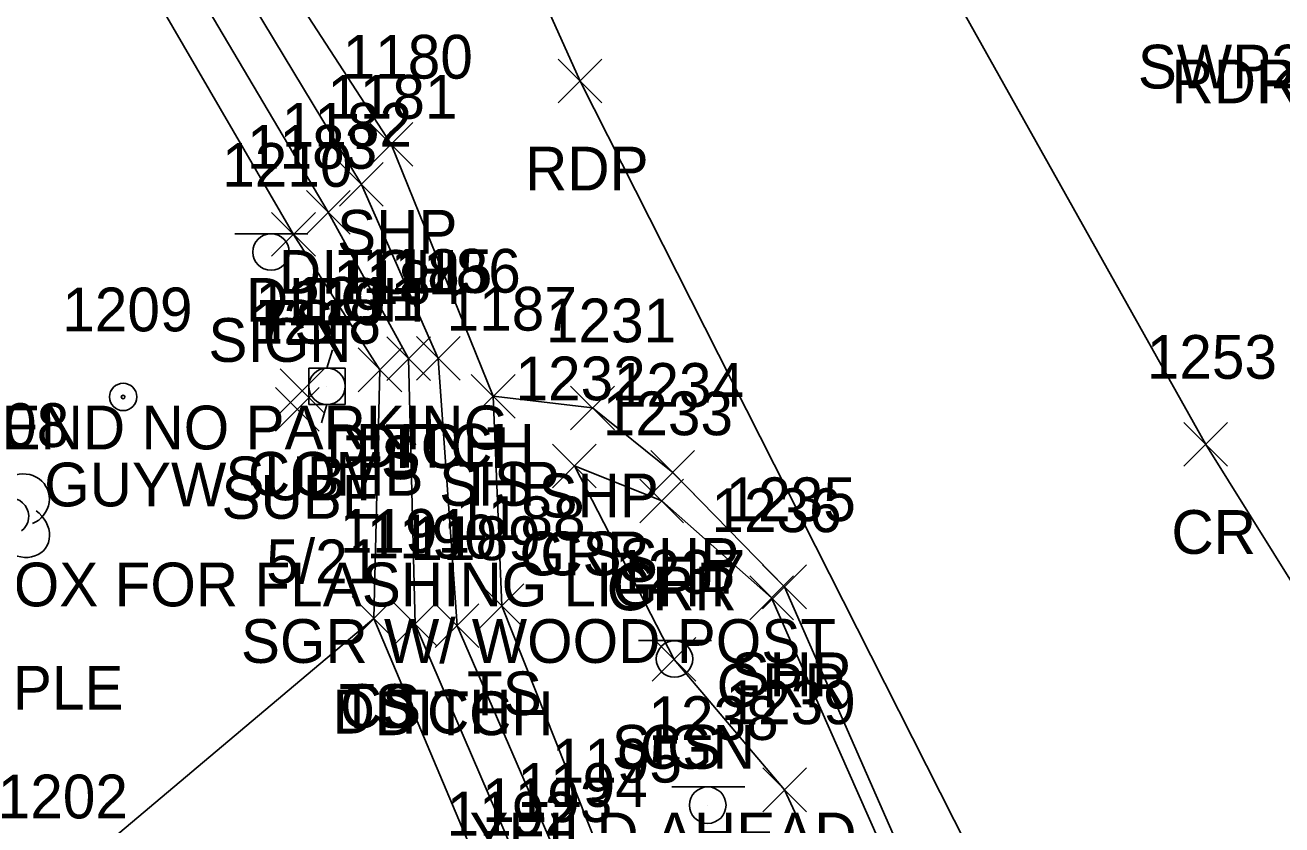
# Model space of a CAD drawing. Extents: x 1504228 to 1506103, y 437717 to 440106.
# Drawn here: x 1505135.1 to 1505192.5, y 438238.1 to 438274.7 of the extents above; entities that cross this region are included whole.
import ezdxf

# ---------------------------------------------------------------- set-up
doc = ezdxf.new("R2010")
doc.units = 0
for name, color, linetype in [('D_A', 7, 'Continuous'), ('D_I', 7, 'Continuous'), ('D_TIC', 7, 'Continuous'), ('DD', 7, 'Continuous'), ('L_A', 7, 'Continuous'), ('L_C', 7, 'Continuous'), ('L_I', 7, 'Continuous'), ('L_TIC', 7, 'Continuous'), ('LELB', 7, 'Continuous'), ('LTD', 7, 'Continuous'), ('P_A', 7, 'Continuous'), ('P_I', 7, 'Continuous'), ('P_TIC', 7, 'Continuous'), ('PET', 7, 'Continuous'), ('PRC', 7, 'Continuous'), ('PSP', 7, 'Continuous'), ('R_A', 7, 'Continuous'), ('R_C', 7, 'Continuous'), ('R_I', 7, 'Continuous'), ('R_TIC', 7, 'Continuous'), ('RGR', 7, 'Continuous'), ('S_A', 7, 'Continuous'), ('S_C', 7, 'Continuous'), ('S_I', 7, 'Continuous'), ('SSGN', 7, 'Continuous'), ('U_A', 7, 'Continuous'), ('U_C', 7, 'Continuous'), ('U_I', 7, 'Continuous'), ('U_TIC', 7, 'Continuous'), ('UP', 7, 'Continuous'), ('UPGW', 7, 'Continuous')]:
    doc.layers.add(name, color=color, linetype=linetype)

msp = doc.modelspace()

# ---------------------------------------------------------------- linework, layer by layer
at = {"layer": 'D_TIC'}
for points in [[(1505149.445, 438266.376), (1505151.445, 438268.376)], [(1505151.445, 438266.376), (1505149.445, 438268.376)], [(1505147.937, 438265.102), (1505149.937, 438267.102)], [(1505149.937, 438265.102), (1505147.937, 438267.102)], [(1505151.605, 438258.415), (1505153.605, 438260.415)], [(1505153.605, 438258.415), (1505151.605, 438260.415)], [(1505152.96, 438258.428), (1505154.96, 438260.428)], [(1505154.96, 438258.428), (1505152.96, 438260.428)], [(1505151.899, 438246.284), (1505153.899, 438248.284)], [(1505153.899, 438246.284), (1505151.899, 438248.284)], [(1505153.819, 438246.207), (1505155.819, 438248.207)], [(1505155.819, 438246.207), (1505153.819, 438248.207)]]:
    msp.add_lwpolyline(points, dxfattribs=at)
at = {"layer": 'DD'}
for points in [[(1505123.23, 438314.656), (1505130.775, 438299.935), (1505150.445, 438267.376), (1505153.96, 438259.428), (1505154.819, 438247.207), (1505159.704, 438235.931), (1505164.132, 438229.451)], [(1505121.248, 438312.943), (1505129.281, 438299.278), (1505148.937, 438266.102), (1505152.605, 438259.415), (1505152.899, 438247.284), (1505158.089, 438235.239), (1505161.473, 438228.418)]]:
    msp.add_lwpolyline(points, dxfattribs=at)
at = {"layer": 'L_TIC'}
for points in [[(1505146.346, 438264.092), (1505148.346, 438266.092)], [(1505148.346, 438264.092), (1505146.346, 438266.092)], [(1505146.346, 438264.092), (1505148.346, 438266.092)], [(1505148.346, 438264.092), (1505146.346, 438266.092)], [(1505150.295, 438257.904), (1505152.295, 438259.904)], [(1505152.295, 438257.904), (1505150.295, 438259.904)], [(1505155.465, 438256.693), (1505157.465, 438258.693)], [(1505157.465, 438256.693), (1505155.465, 438258.693)], [(1505159.179, 438253.51), (1505161.179, 438255.51)], [(1505161.179, 438253.51), (1505159.179, 438255.51)], [(1505155.863, 438247.12), (1505157.863, 438249.12)], [(1505157.863, 438247.12), (1505155.863, 438249.12)], [(1505150.02, 438246.541), (1505152.02, 438248.541)], [(1505152.02, 438246.541), (1505150.02, 438248.541)], [(1505150.02, 438246.541), (1505152.02, 438248.541)], [(1505152.02, 438246.541), (1505150.02, 438248.541)], [(1505163.729, 438244.673), (1505165.729, 438246.673)], [(1505165.729, 438244.673), (1505163.729, 438246.673)], [(1505168.781, 438238.71), (1505170.781, 438240.71)], [(1505170.781, 438238.71), (1505168.781, 438240.71)]]:
    msp.add_lwpolyline(points, dxfattribs=at)
at = {"layer": 'LELB'}
for points in [[(1505072.779, 438294.246), (1505074.28, 438301.778), (1505090.168, 438310.15), (1505097.967, 438315.777), (1505107.308, 438321.068), (1505113.899, 438322.703), (1505119.766, 438311.905), (1505127.938, 438298.439), (1505147.346, 438265.092)], [(1505147.346, 438265.092), (1505151.295, 438258.904), (1505151.02, 438247.541), (1505156.466, 438234.619), (1505159.07, 438229.354), (1505161.306, 438207.965), (1505158.934, 438198.457), (1505143.439, 438200.103), (1505132.424, 438196.394), (1505118.601, 438190.29)], [(1505156.465, 438257.693), (1505156.863, 438248.12), (1505161.265, 438237.042), (1505166.001, 438229.888), (1505173.548, 438226.954), (1505175.53, 438227.278)], [(1505160.179, 438254.51), (1505164.729, 438245.673), (1505169.781, 438239.71), (1505175.53, 438227.278)], [(1505151.02, 438247.541), (1505136.605, 438235.405), (1505116.834, 438228.742), (1505105.312, 438222.915)]]:
    msp.add_lwpolyline(points, dxfattribs=at)
at = {"layer": 'LTD'}
for centre, major_axis, ratio, start_param, end_param in [((1505134.965, 438252.96), (-1.141, -0.483), 0.949671, 1.570796, 4.712389), ((1505134.424, 438252.21), (-0.5, 0.667), 0.989748, 3.141593, 6.283185), ((1505134.924, 438251.543), (-1.09, 0.792), 0.841452, 1.570796, 4.712389)]:
    msp.add_ellipse(centre, major_axis=major_axis, ratio=ratio, start_param=start_param, end_param=end_param, dxfattribs=at)
at = {"layer": 'P_TIC'}
for points in [[(1505159.435, 438271.099), (1505161.435, 438273.099)], [(1505161.435, 438271.099), (1505159.435, 438273.099)], [(1505150.801, 438268.21), (1505152.801, 438270.21)], [(1505152.801, 438268.21), (1505150.801, 438270.21)], [(1505155.465, 438256.693), (1505157.465, 438258.693)], [(1505157.465, 438256.693), (1505155.465, 438258.693)], [(1505160.003, 438256.161), (1505162.003, 438258.161)], [(1505162.003, 438256.161), (1505160.003, 438258.161)], [(1505188.016, 438254.493), (1505190.016, 438256.493)], [(1505190.016, 438254.493), (1505188.016, 438256.493)], [(1505163.671, 438253.213), (1505165.671, 438255.213)], [(1505165.671, 438253.213), (1505163.671, 438255.213)], [(1505168.777, 438247.987), (1505170.777, 438249.987)], [(1505170.777, 438247.987), (1505168.777, 438249.987)]]:
    msp.add_lwpolyline(points, dxfattribs=at)
at = {"layer": 'PET'}
msp.add_lwpolyline([(1505068.915, 438479.856), (1505088.799, 438434.786), (1505098.18, 438413.38), (1505109.535, 438384.969), (1505120.749, 438360.591), (1505130.106, 438339.585), (1505143.01, 438310.872), (1505160.435, 438272.099), (1505181.323, 438230.832), (1505199.453, 438238.762), (1505211.655, 438244.29), (1505203.781, 438257.456), (1505193.868, 438276.083), (1505183.087, 438301.098), (1505168.267, 438328.998), (1505148.647, 438369.04), (1505141.294, 438386.172), (1505109.448, 438444.779), (1505106.082, 438450.67), (1505101.61, 438460.04), (1505094.486, 438475.336), (1505087.609, 438490.541)], dxfattribs=at)
at = {"layer": 'PRC'}
msp.add_lwpolyline([(1505079.068, 438483.546), (1505099.188, 438438.177), (1505118.696, 438394.368), (1505142.43, 438344.291), (1505155.616, 438317.19), (1505174.858, 438280.77), (1505189.016, 438255.493), (1505199.453, 438238.762)], dxfattribs=at)
at = {"layer": 'PSP'}
msp.add_lwpolyline([(1505089.41, 438366.798), (1505096.876, 438357.305), (1505097.995, 438355.39), (1505102.72, 438347.262), (1505117.993, 438324.088), (1505123.23, 438314.656), (1505131.485, 438300.488), (1505151.801, 438269.21), (1505156.465, 438257.693), (1505161.003, 438257.161), (1505164.671, 438254.213), (1505169.777, 438248.987), (1505178.313, 438229.528), (1505181.323, 438230.832)], dxfattribs=at)
at = {"layer": 'R_TIC'}
for points in [[(1505159.179, 438253.51), (1505161.179, 438255.51)], [(1505161.179, 438253.51), (1505159.179, 438255.51)], [(1505163.165, 438251.914), (1505165.165, 438253.914)], [(1505165.165, 438251.914), (1505163.165, 438253.914)], [(1505168.186, 438247.485), (1505170.186, 438249.485)], [(1505170.186, 438247.485), (1505168.186, 438249.485)]]:
    msp.add_lwpolyline(points, dxfattribs=at)
at = {"layer": 'RGR'}
msp.add_lwpolyline([(1505160.179, 438254.51), (1505164.165, 438252.914), (1505169.186, 438248.485), (1505177.609, 438229.457)], dxfattribs=at)
at = {"layer": 'SSGN'}
for p, q in [((1505144.673, 438265.12), (1505148.006, 438265.12)), ((1505146.32, 438264.287), (1505146.32, 438264.287)), ((1505163.102, 438246.527), (1505166.435, 438246.527)), ((1505164.749, 438245.693), (1505164.749, 438245.693)), ((1505164.623, 438239.842), (1505167.956, 438239.842)), ((1505166.27, 438239.009), (1505166.27, 438239.009))]:
    msp.add_line(p, q, dxfattribs=at)
for centre in [(1505146.32, 438264.287), (1505164.749, 438245.693), (1505166.27, 438239.009)]:
    msp.add_circle(centre, 0.833, dxfattribs=at)
at = {"layer": 'U_TIC'}
for points in [[(1505146.743, 438256.943), (1505148.743, 438258.943)], [(1505148.743, 438256.943), (1505146.743, 438258.943)], [(1505146.521, 438256.094), (1505148.521, 438258.094)], [(1505148.521, 438256.094), (1505146.521, 438258.094)]]:
    msp.add_lwpolyline(points, dxfattribs=at)
at = {"layer": 'UP'}
for p, q in [((1505149.125, 438259.817), (1505148.875, 438258.983)), ((1505148.042, 438257.317), (1505148.042, 438258.983)), ((1505148.042, 438258.983), (1505149.708, 438258.983)), ((1505149.708, 438258.983), (1505149.708, 438257.317)), ((1505148.875, 438258.15), (1505148.875, 438258.15)), ((1505149.708, 438257.317), (1505148.042, 438257.317)), ((1505148.625, 438256.483), (1505148.875, 438257.317))]:
    msp.add_line(p, q, dxfattribs=at)
msp.add_circle((1505148.875, 438258.15), 0.833, dxfattribs=at)
at = {"layer": 'UPGW'}
for radius in [0.625, 0.0833]:
    msp.add_circle((1505139.562, 438257.662), radius, dxfattribs=at)

# ---------------------------------------------------------------- texts
at = {"layer": 'D_A'}
for p in [(1505146.681, 438262.376), (1505145.173, 438261.102), (1505148.841, 438254.415), (1505150.196, 438254.428), (1505149.135, 438242.284), (1505151.055, 438242.207)]:
    msp.add_text('DITCH', height=2, dxfattribs=at).set_placement(p)
at = {"layer": 'D_I'}
for s, p in [('1181', (1505148.886, 438270.376)), ('1182', (1505146.811, 438269.102)), ('1185', (1505150.479, 438262.415)), ('1186', (1505151.779, 438262.428)), ('1190', (1505150.686, 438250.284)), ('1189', (1505152.685, 438250.207)), ('1194', (1505157.578, 438238.931)), ('1193', (1505155.963, 438238.239))]:
    msp.add_text(s, height=2, dxfattribs=at).set_placement(p)
at = {"layer": 'L_A'}
for s, p in [('TS', (1505145.755, 438260.092)), ('TS', (1505145.755, 438260.092)), ('TS', (1505149.704, 438253.904)), ('TS', (1505154.874, 438252.693)), ('CS', (1505158.62, 438249.51)), ('TS', (1505155.273, 438243.12)), ('TS', (1505149.429, 438242.541)), ('CS', (1505149.461, 438242.541)), ('CS', (1505163.17, 438240.673))]:
    msp.add_text(s, height=2, dxfattribs=at).set_placement(p)
at = {"layer": 'L_C'}
msp.add_text('M.APPLE', height=2, dxfattribs=at).set_placement((1505127.987, 438243.376))
at = {"layer": 'L_I'}
for s, p in [('1183', (1505145.22, 438268.092)), ('1183', (1505145.22, 438268.092)), ('1184', (1505149.169, 438261.904)), ('1187', (1505154.339, 438260.693)), ('1232', (1505157.486, 438257.51)), ('1208', (1505131.152, 438255.376)), ('1188', (1505154.737, 438251.12)), ('1191', (1505149.461, 438250.541)), ('1191', (1505149.461, 438250.541)), ('1237', (1505162.036, 438248.673)), ('1239', (1505167.08, 438242.71)), ('1195', (1505159.139, 438240.042)), ('1202', (1505133.834, 438238.405)), ('1192', (1505154.34, 438237.619))]:
    msp.add_text(s, height=2, dxfattribs=at).set_placement(p)
at = {"layer": 'P_A'}
for s, p in [('RDP', (1505191.356, 438271.083)), ('RDP', (1505157.923, 438267.099)), ('SHP', (1505149.337, 438264.21)), ('SHP', (1505154, 438252.693)), ('SHP', (1505158.538, 438252.161)), ('CR', (1505187.449, 438250.493)), ('SHP', (1505162.207, 438249.213)), ('SHP', (1505167.313, 438243.987))]:
    msp.add_text(s, height=2, dxfattribs=at).set_placement(p)
at = {"layer": 'P_I'}
for s, p in [('1180', (1505149.589, 438272.21)), ('1187', (1505154.339, 438260.693)), ('1231', (1505158.877, 438260.161)), ('1253', (1505186.323, 438258.493)), ('1234', (1505161.979, 438257.213)), ('1235', (1505167.084, 438251.987))]:
    msp.add_text(s, height=2, dxfattribs=at).set_placement(p)
at = {"layer": 'R_A'}
for s, p in [('SWP2 BS ST', (1505185.915, 438271.759)), ('RDP SWP', (1505187.451, 438271.083)), ('GRR', (1505157.668, 438249.51)), ('GRR', (1505161.654, 438247.914)), ('GRR', (1505166.674, 438243.485))]:
    msp.add_text(s, height=2, dxfattribs=at).set_placement(p)
at = {"layer": 'R_C'}
msp.add_text('SGR W/ WOOD POST', height=2, dxfattribs=at).set_placement((1505144.943, 438245.51))
at = {"layer": 'R_I'}
for s, p in [('1232', (1505157.486, 438257.51)), ('1233', (1505161.473, 438255.914)), ('1236', (1505166.438, 438251.485))]:
    msp.add_text(s, height=2, dxfattribs=at).set_placement(p)
at = {"layer": 'S_A'}
for p in [(1505143.458, 438259.267), (1505161.887, 438240.673)]:
    msp.add_text('SIGN', height=2, dxfattribs=at).set_placement(p)
at = {"layer": 'S_C'}
for s, p in [('END NO PARKING', (1505134.009, 438255.267)), ('YEILD AHEAD', (1505155.383, 438236.673))]:
    msp.add_text(s, height=2, dxfattribs=at).set_placement(p)
at = {"layer": 'S_I'}
for s, p in [('1210', (1505144.088, 438267.267)), ('1237', (1505162.036, 438248.673)), ('1238', (1505163.557, 438241.989))]:
    msp.add_text(s, height=2, dxfattribs=at).set_placement(p)
at = {"layer": 'U_A'}
for s, p in [('GUYW', (1505135.956, 438252.662)), ('SUBT', (1505144.239, 438252.943)), ('COMB', (1505145.261, 438253.15)), ('SUBE', (1505144.056, 438252.094))]:
    msp.add_text(s, height=2, dxfattribs=at).set_placement(p)
at = {"layer": 'U_C'}
for s, p in [('5/21', (1505146.103, 438249.15)), ('METER BOX FOR FLASHING LIGHT', (1505122.678, 438248.094))]:
    msp.add_text(s, height=2, dxfattribs=at).set_placement(p)
at = {"layer": 'U_I'}
for s, p in [('1209', (1505136.783, 438260.662)), ('1219', (1505145.609, 438260.943)), ('1211', (1505147.316, 438261.15)), ('1218', (1505145.395, 438260.094))]:
    msp.add_text(s, height=2, dxfattribs=at).set_placement(p)

doc.saveas('drawing.dxf')
